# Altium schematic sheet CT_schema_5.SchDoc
size 245 x 200 mm
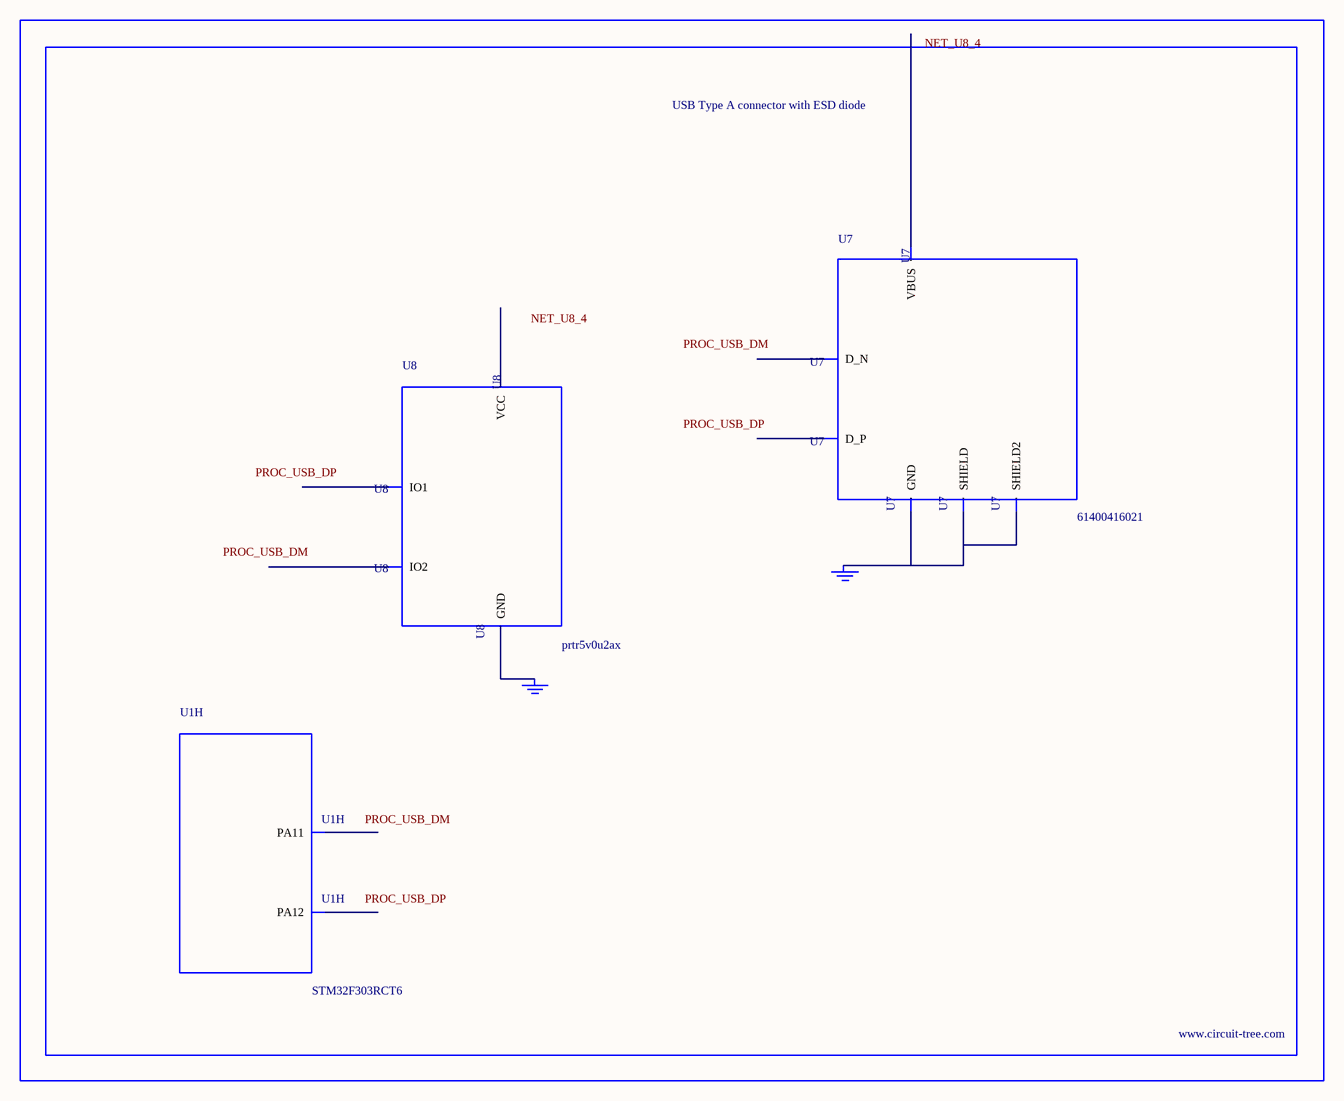
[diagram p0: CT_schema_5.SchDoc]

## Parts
BORDER4  (no value)
GND_INSTANCE_4_0  (no value)
GND_INSTANCE_4_1  (no value)
U1  STM32F303RCT6  [LQFP64]  (part H of 9)
U7  61400416021  [USB-A-H]
U8  prtr5v0u2ax  [SOT143B]

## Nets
NetGND_INSTANCE_4_0_0: GND_INSTANCE_4_0.0(GND) U7.4(GND) U7.5(SHIELD) U7.6(SHIELD2)
NetGND_INSTANCE_4_1_0: GND_INSTANCE_4_1.0(GND) U8.1(GND)

Not connected (* = marked no-connect by the designer): U1 44(PA11) 45(PA12); U7 1(VBUS) 2(D_N) 3(D_P); U8 2(IO1) 3(IO2) 4(VCC)

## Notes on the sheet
- Labels drawn without touching a wire or pin: NET_U8_4, PROC_USB_DM, PROC_USB_DP

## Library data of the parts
BORDER4 = BORDER_PAGE4
GND_INSTANCE_4_0 GND_INSTANCE_4_1 = GND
